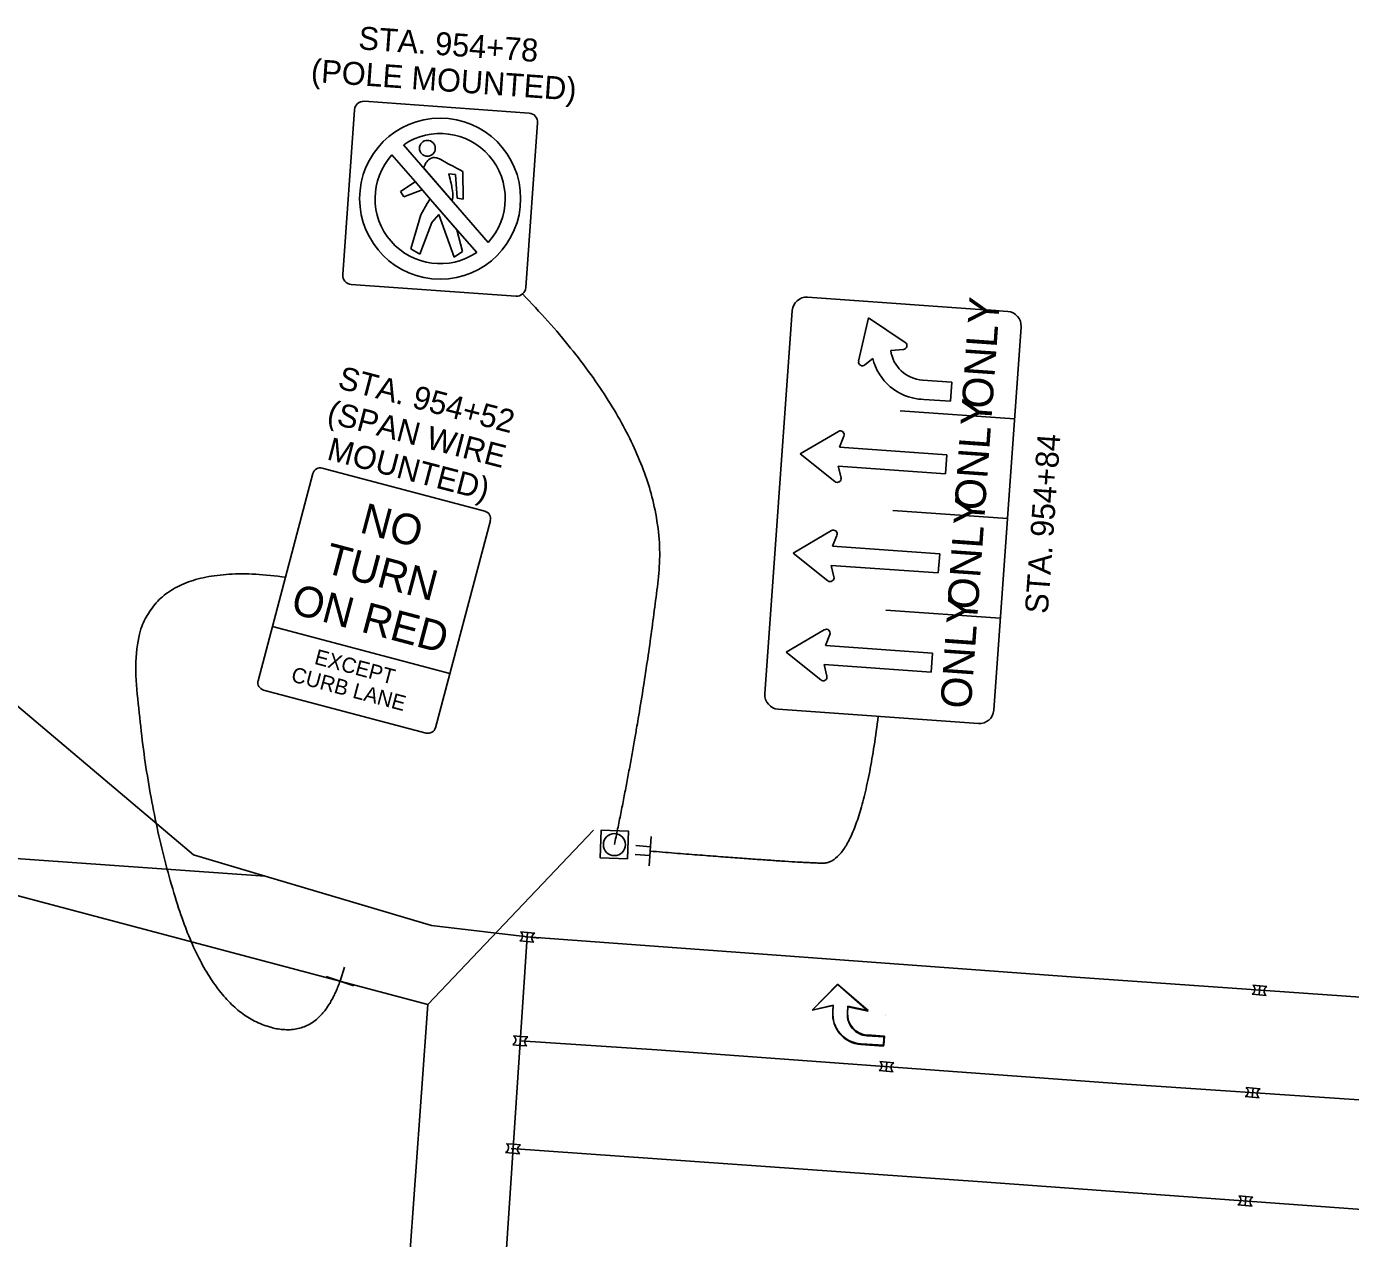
# Model space of a CAD drawing. Extents: x 1847379 to 1850904, y 217032 to 220169.
# Drawn here: x 1849556.2 to 1849700.4, y 218819 to 218951 of the extents above; entities that cross this region are included whole.
import ezdxf

# ---------------------------------------------------------------- set-up
doc = ezdxf.new("R2010")
doc.units = 0
for name, color, linetype in [('BR_P_Gen_Approach_Slab_Hidden', 7, 'Continuous'), ('BR_P_Gen_Phase_Construction', 7, 'Continuous'), ('PM_P_Cells', 7, 'Continuous'), ('PM_P_Channelizing_Line', 7, 'Continuous'), ('PM_P_Edge_Line', 7, 'Continuous'), ('PM_P_Lane_Line', 7, 'Continuous'), ('PM_P_Stop_Line', 7, 'Continuous'), ('PM_X_Cells', 7, 'Continuous'), ('SG_X_Wiring', 7, 'Continuous'), ('SN_X_Foundation', 7, 'Continuous'), ('SN_X_Public', 7, 'Continuous'), ('SN_X_Text', 7, 'Continuous')]:
    doc.layers.add(name, color=color, linetype=linetype)

msp = doc.modelspace()

# ---------------------------------------------------------------- linework, layer by layer
at = {"layer": 'BR_P_Gen_Approach_Slab_Hidden'}
for p, q in [((1849574.36, 218860.81), (1849554.17, 218877.89)), ((1849582.2, 218858.48), (1849574.36, 218860.81))]:
    msp.add_line(p, q, dxfattribs=at)
at = {"layer": 'BR_P_Gen_Phase_Construction'}
msp.add_line((1849509.39, 218863.67), (1849582.2, 218858.48), dxfattribs=at)
at = {"layer": 'PM_P_Cells'}
for p, q in [((1849609.92, 218851.45), (1849610.69, 218851.38)), ((1849609.92, 218851.45), (1849610.69, 218851.38)), ((1849610.78, 218852.35), (1849610.01, 218852.42)), ((1849610.01, 218852.42), (1849610.78, 218852.35)), ((1849610.69, 218851.38), (1849610.78, 218852.35)), ((1849610.69, 218851.38), (1849611.46, 218851.31)), ((1849610.78, 218852.35), (1849611.55, 218852.28)), ((1849641.8, 218843.88), (1849644.54, 218846.72)), ((1849644.54, 218846.72), (1849647.89, 218843.85)), ((1849689.71, 218845.64), (1849690.48, 218845.57)), ((1849689.71, 218845.64), (1849690.48, 218845.57)), ((1849690.57, 218846.54), (1849689.8, 218846.61)), ((1849689.8, 218846.61), (1849690.57, 218846.54)), ((1849690.48, 218845.57), (1849690.57, 218846.54)), ((1849690.48, 218845.57), (1849691.25, 218845.5)), ((1849690.57, 218846.54), (1849691.34, 218846.47)), ((1849644.08, 218844.42), (1849641.8, 218843.88)), ((1849644.04, 218843.75), (1849644.08, 218844.42)), ((1849645.68, 218844.32), (1849645.63, 218843.62)), ((1849647.89, 218843.85), (1849645.68, 218844.32)), ((1849641.8, 218843.88), (1849641.8, 218843.88)), ((1849649.79, 218843.4), (1849649.79, 218843.4)), ((1849609.17, 218840.13), (1849609.93, 218840.06)), ((1849609.17, 218840.13), (1849609.93, 218840.06)), ((1849610.02, 218841.04), (1849609.25, 218841.1)), ((1849609.25, 218841.1), (1849610.02, 218841.04)), ((1849609.93, 218840.06), (1849610.02, 218841.04)), ((1849609.93, 218840.06), (1849610.7, 218839.99)), ((1849610.02, 218841.04), (1849610.79, 218840.97)), ((1849649.59, 218840.08), (1849647.11, 218840.22)), ((1849647.79, 218841.19), (1849649.65, 218841.07)), ((1849649.65, 218841.07), (1849649.59, 218840.08)), ((1849649.07, 218837.32), (1849649.84, 218837.25)), ((1849649.07, 218837.32), (1849649.84, 218837.25)), ((1849649.92, 218838.22), (1849649.16, 218838.29)), ((1849649.16, 218838.29), (1849649.92, 218838.22)), ((1849649.84, 218837.25), (1849649.92, 218838.22)), ((1849649.84, 218837.25), (1849650.6, 218837.18)), ((1849649.92, 218838.22), (1849650.69, 218838.15)), ((1849689.82, 218835.39), (1849689.06, 218835.46)), ((1849689.06, 218835.46), (1849689.82, 218835.39)), ((1849688.97, 218834.49), (1849689.74, 218834.42)), ((1849688.97, 218834.49), (1849689.74, 218834.42)), ((1849689.74, 218834.42), (1849689.82, 218835.39)), ((1849689.74, 218834.42), (1849690.5, 218834.35)), ((1849689.82, 218835.39), (1849690.59, 218835.32)), ((1849608.38, 218828.38), (1849609.15, 218828.31)), ((1849608.38, 218828.38), (1849609.15, 218828.31)), ((1849609.24, 218829.28), (1849608.47, 218829.35)), ((1849608.47, 218829.35), (1849609.24, 218829.28)), ((1849609.15, 218828.31), (1849609.24, 218829.28)), ((1849609.15, 218828.31), (1849609.92, 218828.24)), ((1849609.24, 218829.28), (1849610.01, 218829.22)), ((1849688.18, 218822.69), (1849688.95, 218822.62)), ((1849688.18, 218822.69), (1849688.95, 218822.62)), ((1849689.04, 218823.6), (1849688.27, 218823.66)), ((1849688.27, 218823.66), (1849689.04, 218823.6)), ((1849688.95, 218822.62), (1849689.04, 218823.6)), ((1849688.95, 218822.62), (1849689.72, 218822.55)), ((1849689.04, 218823.6), (1849689.8, 218823.53))]:
    msp.add_line(p, q, dxfattribs=at)
for centre, radius, start, end in [((1849609.66, 218851.96), 0.576, 296.8063, 52.8586), ((1849609.66, 218851.96), 0.576, 296.8063, 52.8586), ((1849611.81, 218851.77), 0.576, 116.8063, 232.8586), ((1849689.45, 218846.15), 0.576, 296.8063, 52.8586), ((1849689.45, 218846.15), 0.576, 296.8063, 52.8586), ((1849691.6, 218845.96), 0.576, 116.8063, 232.8586), ((1849647.31, 218843.5), 3.28, 175.6389, 266.5474), ((1849647.93, 218843.48), 2.3, 176.5474, 266.5474), ((1849608.91, 218840.65), 0.576, 296.8063, 52.8586), ((1849608.91, 218840.65), 0.576, 296.8063, 52.8586), ((1849611.05, 218840.45), 0.576, 116.8063, 232.8586), ((1849648.81, 218837.83), 0.576, 296.8063, 52.8586), ((1849648.81, 218837.83), 0.576, 296.8063, 52.8586), ((1849650.95, 218837.64), 0.576, 116.8063, 232.8586), ((1849688.71, 218835), 0.576, 296.8063, 52.8586), ((1849688.71, 218835), 0.576, 296.8063, 52.8586), ((1849690.85, 218834.81), 0.576, 116.8063, 232.8586), ((1849608.12, 218828.9), 0.576, 296.8063, 52.8586), ((1849608.12, 218828.9), 0.576, 296.8063, 52.8586), ((1849610.26, 218828.7), 0.576, 116.8063, 232.8586), ((1849687.92, 218823.21), 0.576, 296.8063, 52.8586), ((1849687.92, 218823.21), 0.576, 296.8063, 52.8586), ((1849690.06, 218823.01), 0.576, 116.8063, 232.8586)]:
    msp.add_arc(centre, radius, start, end, dxfattribs=at)
at = {"layer": 'PM_P_Channelizing_Line'}
msp.add_lwpolyline([(1849773.98, 218829.08), (1849727.27, 218832.37), (1849675.5, 218835.87), (1849624.87, 218839.56), (1849609.96, 218840.55)], dxfattribs=at)
at = {"layer": 'PM_P_Edge_Line'}
for p, q in [((1849582.2, 218858.48), (1849600.3, 218853.1)), ((1849600.3, 218853.1), (1849612.02, 218851.75))]:
    msp.add_line(p, q, dxfattribs=at)
msp.add_lwpolyline([(1849891.07, 218821.31), (1849889.22, 218821.46), (1849832.32, 218830.92), (1849780.01, 218839.12), (1849775.45, 218839.9), (1849724.32, 218843.71), (1849670.97, 218847.45), (1849610.73, 218851.87), (1849610.54, 218851.85)], dxfattribs=at)
at = {"layer": 'PM_P_Lane_Line'}
msp.add_lwpolyline([(1849608.99, 218828.81), (1849660.31, 218825.18), (1849710.18, 218821.58), (1849761.09, 218817.87), (1849808.06, 218814.41), (1849858.45, 218811.1), (1849907.69, 218807.67), (1849958.4, 218803.79), (1850015.55, 218799.15), (1850068.16, 218794.66), (1850119.07, 218790.16), (1850168.5, 218785.91), (1850217.76, 218781.65), (1850267.02, 218777.03), (1850317.3, 218772.15), (1850366.38, 218767.35), (1850416.59, 218762.59), (1850466.65, 218757.55), (1850517.86, 218752.55), (1850566.57, 218747.88), (1850616.29, 218742.91), (1850664.9, 218737.75)], dxfattribs=at)
at = {"layer": 'PM_P_Stop_Line'}
msp.add_line((1849610.73, 218851.87), (1849607.64, 218805.52), dxfattribs=at)
at = {"layer": 'PM_X_Cells'}
for p, q in [((1849641.8, 218843.88), (1849644.57, 218846.69)), ((1849644.57, 218846.69), (1849647.89, 218843.78)), ((1849644.09, 218844.39), (1849641.8, 218843.88)), ((1849644.04, 218843.72), (1849644.09, 218844.39)), ((1849645.68, 218844.27), (1849645.63, 218843.57)), ((1849647.89, 218843.78), (1849645.68, 218844.27)), ((1849641.8, 218843.88), (1849641.8, 218843.88)), ((1849649.78, 218843.3), (1849649.78, 218843.3)), ((1849649.54, 218839.98), (1849647.07, 218840.16)), ((1849647.75, 218841.11), (1849649.61, 218840.98)), ((1849649.61, 218840.98), (1849649.54, 218839.98))]:
    msp.add_line(p, q, dxfattribs=at)
for centre, radius, start in [((1849647.31, 218843.43), 3.28, 174.927), ((1849647.92, 218843.4), 2.3, 175.8355)]:
    msp.add_arc(centre, radius, start, 265.8355, dxfattribs=at)
at = {"layer": 'SG_X_Wiring'}
for p, q in [((1849498.77, 218871.29), (1849599.9, 218844.52)), ((1849599.9, 218844.52), (1849617.95, 218863.48)), ((1849593, 218747.62), (1849599.9, 218844.52))]:
    msp.add_line(p, q, dxfattribs=at)
at = {"layer": 'SN_X_Foundation'}
msp.add_lwpolyline([(1849621.68, 218860.38), (1849621.79, 218863.38), (1849618.79, 218863.49), (1849618.68, 218860.49)], close=True, dxfattribs=at)
msp.add_circle((1849620.24, 218861.93), 1.2, dxfattribs=at)
at = {"layer": 'SN_X_Public'}
for p, q in [((1849597.27, 218938.16), (1849606.49, 218927.51)), ((1849599.44, 218935.65), (1849599.54, 218935.54)), ((1849599.54, 218935.54), (1849602.52, 218932.1)), ((1849603.73, 218935.24), (1849603.71, 218935.24)), ((1849603.73, 218935.24), (1849603.71, 218935.24)), ((1849603.74, 218932.24), (1849603.73, 218935.24)), ((1849603.74, 218932.24), (1849603.73, 218935.24)), ((1849598.54, 218934.13), (1849596.92, 218933.08)), ((1849598.54, 218934.13), (1849596.92, 218933.08)), ((1849602.2, 218934.98), (1849602.93, 218934.9)), ((1849602.2, 218934.98), (1849602.93, 218934.9)), ((1849602.93, 218934.9), (1849603.11, 218932.34)), ((1849602.93, 218934.9), (1849603.11, 218932.34)), ((1849596.92, 218933.08), (1849597.28, 218932.47)), ((1849596.92, 218933.08), (1849597.28, 218932.47)), ((1849597.28, 218932.47), (1849599.3, 218933.24)), ((1849597.28, 218932.47), (1849599.3, 218933.24)), ((1849599.3, 218933.24), (1849599.15, 218933.42)), ((1849600.16, 218932.26), (1849599.85, 218931.77)), ((1849600.16, 218932.26), (1849599.85, 218931.77)), ((1849600.21, 218932.2), (1849600.16, 218932.26)), ((1849603.07, 218928.9), (1849600.21, 218932.2)), ((1849603.11, 218932.34), (1849603.74, 218932.24)), ((1849603.11, 218932.34), (1849603.74, 218932.24)), ((1849599.85, 218931.77), (1849599.16, 218930.53)), ((1849599.85, 218931.77), (1849599.16, 218930.53)), ((1849599.16, 218930.53), (1849598.06, 218926.83)), ((1849599.16, 218930.53), (1849598.06, 218926.83)), ((1849599.05, 218926.24), (1849600.35, 218929.69)), ((1849599.05, 218926.24), (1849600.35, 218929.69)), ((1849600.35, 218929.69), (1849601.12, 218930.54)), ((1849600.35, 218929.69), (1849601.12, 218930.54)), ((1849601.12, 218930.54), (1849602.77, 218925.9)), ((1849601.12, 218930.54), (1849602.77, 218925.9)), ((1849603.7, 218926.51), (1849603.07, 218928.9)), ((1849603.7, 218926.51), (1849603.07, 218928.9)), ((1849598.06, 218926.83), (1849599.05, 218926.24)), ((1849598.06, 218926.83), (1849599.05, 218926.24)), ((1849602.77, 218925.9), (1849603.7, 218926.51)), ((1849602.77, 218925.9), (1849603.7, 218926.51)), ((1849646.85, 218914.58), (1849647.91, 218919.3)), ((1849647.91, 218919.3), (1849651.93, 218916.63)), ((1849648.38, 218914.87), (1849647.52, 218914.17)), ((1849651.74, 218915.86), (1849650.34, 218915.75)), ((1849653.79, 218912.52), (1849657.01, 218912.29)), ((1849657.01, 218912.29), (1849656.87, 218910.21)), ((1849663.83, 218908.3), (1849651.36, 218909.19)), ((1849656.87, 218910.21), (1849653.38, 218910.46)), ((1849653.38, 218910.46), (1849653.64, 218910.43)), ((1849644.65, 218906.93), (1849640.48, 218904.48)), ((1849644.78, 218905.22), (1849645.25, 218906.42)), ((1849656.45, 218904.39), (1849644.78, 218905.22)), ((1849640.48, 218904.48), (1849644.26, 218901.47)), ((1849656.3, 218902.31), (1849656.45, 218904.39)), ((1849644.93, 218901.89), (1849644.63, 218903.14)), ((1849644.63, 218903.14), (1849656.3, 218902.31)), ((1849663.06, 218897.44), (1849650.59, 218898.33)), ((1849643.88, 218896.13), (1849639.71, 218893.68)), ((1849644.01, 218894.42), (1849644.48, 218895.61)), ((1849639.71, 218893.68), (1849643.49, 218890.66)), ((1849655.68, 218893.58), (1849644.01, 218894.42)), ((1849655.53, 218891.51), (1849655.68, 218893.58)), ((1849644.16, 218891.08), (1849643.86, 218892.34)), ((1849643.86, 218892.34), (1849655.53, 218891.51)), ((1849662.28, 218886.58), (1849649.81, 218887.47)), ((1849602.31, 218880.56), (1849582.97, 218885.67)), ((1849643.11, 218885.32), (1849638.94, 218882.87)), ((1849643.24, 218883.61), (1849643.71, 218884.81)), ((1849654.91, 218882.78), (1849643.24, 218883.61)), ((1849638.94, 218882.87), (1849642.72, 218879.86)), ((1849654.76, 218880.7), (1849654.91, 218882.78)), ((1849643.39, 218880.28), (1849643.09, 218881.53)), ((1849643.09, 218881.53), (1849654.76, 218880.7)), ((1849624.17, 218861.69), (1849622.58, 218861.82)), ((1849624.26, 218862.81), (1849624.01, 218859.62)), ((1849624.1, 218860.74), (1849622.5, 218860.86)), ((1849624.14, 218861.21), (1849624.14, 218861.21)), ((1849590.34, 218847.06), (1849590.84, 218848.58)), ((1849591.86, 218846.56), (1849588.82, 218847.56))]:
    msp.add_line(p, q, dxfattribs=at)
for points in [[(1849610.94, 218941.61), (1849592.98, 218942.89)], [(1849591.91, 218941.96), (1849590.63, 218924.01)], [(1849610.58, 218922.59), (1849611.86, 218940.54)], [(1849596, 218937.05), (1849598.51, 218934.16), (1849599.15, 218933.43), (1849599.15, 218933.42)], [(1849599.54, 218935.54), (1849599.54, 218935.54)], [(1849599.15, 218933.42), (1849598.54, 218934.13), (1849598.54, 218934.13)], [(1849599.15, 218933.42), (1849600.21, 218932.2), (1849603.65, 218928.24), (1849605.23, 218926.42)], [(1849591.56, 218922.94), (1849609.51, 218921.66)], [(1849641.28, 218921.55), (1849663.1, 218920)], [(1849636.63, 218878.34), (1849639.61, 218920.11)], [(1849664.55, 218918.33), (1849661.57, 218876.56)], [(1849587.38, 218902.34), (1849581.41, 218879.78)], [(1849606.13, 218898.24), (1849588.4, 218902.93)], [(1849600.75, 218874.66), (1849606.72, 218897.22)], [(1849582.01, 218878.76), (1849599.73, 218874.07)], [(1849659.9, 218875.11), (1849638.08, 218876.67)]]:
    msp.add_lwpolyline(points, dxfattribs=at)
for centre, radius in [((1849601.25, 218932.29), 8.77), ((1849599.86, 218937.77), 0.864)]:
    msp.add_circle(centre, radius, dxfattribs=at)
for centre, radius, start, end in [((1849592.91, 218941.89), 1, 85.9213, 175.9213), ((1849610.86, 218940.61), 1, 355.9213, 85.9213), ((1849601.25, 218932.29), 7.09, 317.7404, 124.0927), ((1849601.25, 218932.29), 7.09, 137.7693, 304.1693), ((1849601.25, 218932.29), 7.09, 137.7693, 304.1693), ((1849591.63, 218923.94), 1, 175.9213, 265.9213), ((1849609.58, 218922.66), 1, 265.9213, 355.9213), ((1849641.17, 218919.99), 1.56, 85.9213, 175.9213), ((1849662.99, 218918.44), 1.56, 355.9213, 85.9213), ((1849651.7, 218916.28), 0.417, 274.536, 56.4141), ((1849654.06, 218916.26), 5.84, 193.6893, 265.9213), ((1849654.06, 218916.26), 3.75, 187.6981, 265.9213), ((1849647.26, 218914.49), 0.417, 167.3816, 309.2597), ((1849644.86, 218906.57), 0.417, 338.5595, 120.4376), ((1849588.19, 218902.13), 0.833, 75.1733, 165.1733), ((1849644.52, 218901.79), 0.417, 231.4051, 13.2832), ((1849605.91, 218897.43), 0.833, 345.1733, 75.1733), ((1849644.09, 218895.77), 0.417, 338.5595, 120.4376), ((1849643.75, 218890.99), 0.417, 231.4051, 13.2832), ((1849643.32, 218884.96), 0.417, 338.5595, 120.4376), ((1849642.98, 218880.18), 0.417, 231.4051, 13.2832), ((1849582.22, 218879.57), 0.833, 165.1733, 255.1733), ((1849638.19, 218878.23), 1.56, 175.9213, 265.9213), ((1849660.01, 218876.67), 1.56, 265.9213, 355.9213), ((1849599.94, 218874.88), 0.833, 255.1733, 345.1733)]:
    msp.add_arc(centre, radius, start, end, dxfattribs=at)
for points, degree in [([(1849603.71, 218935.24), (1849602.86, 218935.69), (1849601.52, 218936.42), (1849601.03, 218936.69), (1849600.86, 218936.74), (1849600.69, 218936.75), (1849600.29, 218936.78), (1849599.76, 218936.34), (1849599.57, 218935.92), (1849599.44, 218935.65)], 3), ([(1849603.71, 218935.24), (1849602.86, 218935.69), (1849601.52, 218936.42), (1849601.03, 218936.69), (1849600.86, 218936.74), (1849600.69, 218936.75), (1849600.29, 218936.78), (1849599.76, 218936.34), (1849599.57, 218935.92), (1849599.44, 218935.65)], 3), ([(1849602.52, 218932.1), (1849602.56, 218932.17), (1849602.64, 218932.37), (1849602.64, 218932.83), (1849602.58, 218933.25), (1849602.44, 218933.98), (1849602.32, 218934.49), (1849602.2, 218934.98)], 3), ([(1849602.52, 218932.1), (1849602.56, 218932.17), (1849602.64, 218932.37), (1849602.64, 218932.83), (1849602.58, 218933.25), (1849602.44, 218933.98), (1849602.32, 218934.49), (1849602.2, 218934.98)], 3), ([(1849590.34, 218847.06), (1849587.91, 218840.09), (1849576.07, 218844.48), (1849569.1, 218866.61), (1849567.16, 218893.41), (1849584.4, 218891.06)], 2)]:
    msp.add_open_spline(points, degree=degree, dxfattribs=at)
at = {"layer": 'SN_X_Text'}
for points in [[(1849620.24, 218861.93), (1849623.37, 218876.89), (1849626.67, 218904.92), (1849610.24, 218921.9)], [(1849624.14, 218861.21), (1849638.78, 218860.03), (1849646.94, 218859.77), (1849648.99, 218875.89)]]:
    msp.add_open_spline(points, degree=2, dxfattribs=at)

# ---------------------------------------------------------------- texts
at = {"layer": 'SN_X_Public'}
for s, height, rotation, p in [('STA. 954+78', 2.5, 355.9213, (1849592.29, 218948.56)), ('(POLE MOUNTED)', 2.5, 355.9213, (1849587.12, 218945.01)), ('ONLY', 3.333, 85.9213, (1849661.4, 218909.32)), ('ONLY', 3.333, 85.9213, (1849660.61, 218898.27)), ('NO', 3.333, 345.1733, (1849592.36, 218895.96)), ('ONLY', 3.333, 85.9213, (1849659.84, 218887.46)), ('TURN', 3.333, 345.1733, (1849588.46, 218891.6)), ('ON RED', 3.333, 345.1733, (1849584.84, 218887.17)), ('ONLY', 3.333, 85.9213, (1849659.07, 218876.65)), ('EXCEPT', 1.667, 345.1733, (1849587.45, 218881.63)), ('CURB LANE', 1.667, 345.1733, (1849584.91, 218879.72))]:
    msp.add_text(s, height=height, rotation=rotation, dxfattribs=at).set_placement(p)
at = {"layer": 'SN_X_Text'}
for s, rotation, p in [('STA. 954+52', 345.3989, (1849589.98, 218911.66)), ('(SPAN WIRE ', 345.3989, (1849588.79, 218907.94)), ('MOUNTED)', 345.3989, (1849588.8, 218903.91)), ('STA. 954+84', 85.9213, (1849667.45, 218887.01))]:
    msp.add_text(s, height=2.5, rotation=rotation, dxfattribs=at).set_placement(p)

doc.saveas('drawing.dxf')
